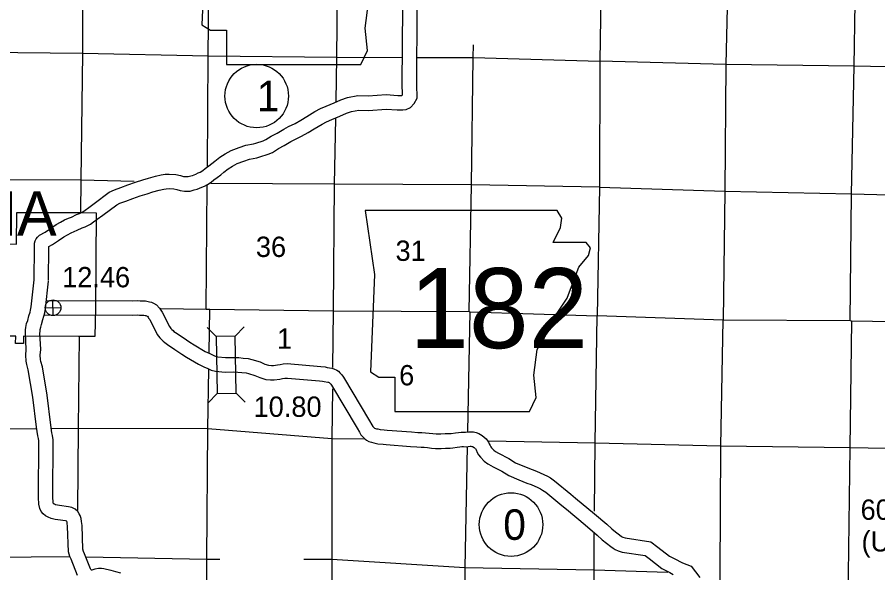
# Model space of a CAD drawing. Extents: x 369523 to 838377, y 495025 to 936819.
# Drawn here: x 502826 to 538589, y 719688 to 742775 of the extents above; entities that cross this region are included whole.
import ezdxf

# ---------------------------------------------------------------- set-up
doc = ezdxf.new("R2010")
doc.units = 0
for name, color, linetype in [('22', 7, 'Continuous'), ('DSN_BRDG_Annotation', 7, 'Continuous'), ('DSN_DRFT_Common-Annotations', 7, 'Continuous'), ('DSN_DRFT_Common-Line', 7, 'Continuous'), ('DSN_DRFT_Junk-No-Plot', 7, 'Continuous'), ('Level 1', 7, 'Continuous'), ('Level 15', 7, 'Continuous'), ('Level 2', 7, 'Continuous'), ('Level 21', 7, 'Continuous'), ('Level 22', 7, 'Continuous')]:
    doc.layers.add(name, color=color, linetype=linetype)

msp = doc.modelspace()

# ---------------------------------------------------------------- linework, layer by layer
at = {"layer": '22'}
for points in [[(510274, 749165), (510674, 746501), (510496, 742460), (510852, 742237), (511518, 742237), (511518, 740816), (517113, 740816), (517380, 741394), (517291, 742326), (517424, 743392), (517913, 744236), (518223, 744858), (518668, 745524), (518934, 746234), (519156, 746812), (519556, 747300), (519645, 747611), (519467, 747833), (518090, 747833), (518401, 748455), (518446, 748854), (518261, 749161)], [(517281, 734741), (517681, 732077), (517504, 728036), (517859, 727814), (518525, 727814), (518525, 726392), (524121, 726392), (524387, 726970), (524298, 727902), (524431, 728968), (524920, 729812), (525231, 730434), (525675, 731100), (525941, 731810), (526163, 732388), (526563, 732876), (526652, 733187), (526474, 733409), (525098, 733409), (525408, 734031), (525453, 734431), (525269, 734737)]]:
    msp.add_lwpolyline(points, close=True, dxfattribs=at)
at = {"layer": 'DSN_DRFT_Common-Annotations'}
for p, q in [((504322, 730377), (504307, 731028)), ((503989, 730695), (504640, 730710))]:
    msp.add_line(p, q, dxfattribs=at)
msp.add_circle((504315, 730703), 326, dxfattribs=at)
at = {"layer": 'DSN_DRFT_Common-Line'}
for centre in [(512780, 739499), (523347, 721691)]:
    msp.add_circle(centre, 1320, dxfattribs=at)
at = {"layer": 'Level 1'}
for points in [[(503524, 731839), (503546, 733218), (503546, 733319), (503549, 733383), (503570, 733478), (503611, 733560), (503663, 733635), (503749, 733713), (503982, 733846), (504209, 733992), (504444, 734159), (504631, 734261), (504797, 734349), (504964, 734425), (505083, 734470), (505290, 734573), (505420, 734618), (505552, 734684), (505644, 734753), (505804, 734864), (506030, 735032), (506648, 735499), (506868, 735604), (507137, 735697), (507421, 735805), (507742, 735923), (508045, 736014), (508285, 736090), (508577, 736172), (508809, 736226), (508968, 736246), (509147, 736256), (509414, 736237), (509615, 736201), (509731, 736161), (509821, 736149), (509929, 736150), (510041, 736179), (510112, 736196), (510250, 736257), (510351, 736302), (510431, 736341), (510534, 736408), (510635, 736492), (510785, 736597), (510909, 736689), (511034, 736796), (511246, 736960), (511470, 737101), (511715, 737239), (512047, 737363), (512333, 737453), (512647, 737520), (512747, 737547), (513051, 737642), (513157, 737687), (513385, 737830), (513623, 737963), (513901, 738129), (514094, 738230), (514371, 738361), (514615, 738499), (514861, 738645), (515201, 738858), (515428, 738975), (515664, 739076), (515997, 739212), (516274, 739337), (516557, 739444), (516982, 739515), (517414, 739503), (518153, 739562), (518644, 739523), (518723, 739524), (518807, 739527), (518822, 739529), (518835, 739545), (518844, 739560), (518830, 739991), (518853, 743187)], [(504124, 731829), (504146, 733214), (504146, 733249), (504294, 733333), (504545, 733494), (504763, 733649), (504915, 733733), (505063, 733811), (505195, 733871), (505323, 733920), (505522, 734019), (505651, 734063), (505869, 734171), (505996, 734267), (506154, 734377), (506390, 734552), (506962, 734983), (507097, 735048), (507342, 735133), (507631, 735243), (507932, 735353), (508222, 735440), (508457, 735515), (508727, 735591), (508914, 735635), (509022, 735648), (509142, 735655), (509338, 735641), (509464, 735618), (509592, 735574), (509785, 735548), (510009, 735552), (510184, 735596), (510304, 735625), (510493, 735709), (510603, 735757), (510729, 735819), (510890, 735925), (510999, 736014), (511136, 736111), (511283, 736220), (511412, 736330), (511590, 736468), (511776, 736585), (511969, 736693), (512242, 736796), (512486, 736872), (512787, 736936), (512914, 736971), (513259, 737078), (513436, 737154), (513690, 737314), (513922, 737443), (514193, 737604), (514362, 737693), (514647, 737828), (514916, 737980), (515173, 738133), (515498, 738336), (515684, 738432), (515895, 738522), (516235, 738661), (516504, 738782), (516714, 738862), (517023, 738914), (517429, 738902), (518154, 738960), (518621, 738923), (518737, 738924), (518857, 738929), (518993, 738946), (519172, 739020), (519327, 739194), (519449, 739412), (519430, 739998), (519453, 743157)], [(503400, 730738), (503526, 731867)], [(503997, 730671), (504122, 731801)], [(504041, 731004), (507603, 730994), (507824, 731003), (507932, 730994), (508069, 730994), (508162, 730983), (508266, 730968), (508327, 730953), (508402, 730930), (508494, 730892), (508612, 730821), (508746, 730681), (508796, 730595), (508851, 730513), (509153, 729921), (509215, 729842), (509258, 729796), (509302, 729757), (509340, 729719), (509411, 729672), (509722, 729465), (509994, 729273), (510179, 729157), (510641, 728884), (510829, 728798), (510996, 728723), (511090, 728680), (511165, 728660), (511486, 728629), (511823, 728635), (512037, 728630), (512217, 728610), (512428, 728589), (512583, 728556), (512919, 728450), (513122, 728360), (513265, 728315), (513394, 728307), (513471, 728303), (513639, 728329), (513760, 728350), (513882, 728365), (514049, 728382), (515442, 728261), (515630, 728244), (515708, 728221), (515899, 728198), (515949, 728175), (515988, 728162), (516112, 728103), (516177, 728061), (516231, 727999), (516311, 727917), (516382, 727823), (517469, 726001), (517559, 725839), (517607, 725766), (517638, 725740), (517678, 725701), (517680, 725699), (517716, 725687), (517762, 725675), (517810, 725669), (517908, 725646), (518081, 725630), (518203, 725620), (519211, 725540), (519476, 725520), (519645, 725512), (519792, 725501), (519942, 725486), (520103, 725470), (520241, 725457), (520429, 725459), (520608, 725471), (520775, 725470), (520855, 725482), (521036, 725506), (521160, 725520), (521272, 725532), (521381, 725532), (521459, 725530), (521599, 725546), (521701, 725552), (521794, 725541), (521906, 725513), (522011, 725470), (522145, 725389), (522236, 725324), (522321, 725251), (522409, 725120), (522441, 725044), (522476, 724972), (522505, 724924), (522536, 724881), (522633, 724781), (522709, 724724), (522834, 724653)], [(505333, 719570), (505062, 720258), (505018, 720370), (504954, 720557), (504920, 721611), (504908, 721744), (504899, 721798), (504892, 721821), (504885, 721832), (504830, 721847), (504515, 721895), (504410, 721904), (504236, 721943), (504107, 721997), (503999, 722060), (503908, 722133), (503826, 722236), (503767, 722359), (503726, 722536), (503706, 722817), (503723, 725173), (503709, 725270), (503681, 725379), (503625, 725746), (503471, 726981), (503286, 728118), (503224, 728347), (503204, 728485), (503186, 728728), (503200, 728964), (503165, 729655), (503177, 729782), (503189, 729879), (503219, 730047), (503262, 730174), (503313, 730372), (503360, 730525), (503384, 730608), (503401, 730743)], [(507126, 719667), (506925, 719729), (506729, 719777), (506537, 719825), (506424, 719848), (506324, 719864), (506208, 719860), (506056, 719837), (505921, 719797), (505911, 719803), (505885, 719825), (505868, 719850), (505621, 720477), (505581, 720578), (505550, 720667), (505519, 721648), (505503, 721819), (505484, 721938), (505444, 722063), (505404, 722134), (505347, 722238), (505230, 722339), (505099, 722397), (504951, 722435), (504587, 722491), (504500, 722499), (504419, 722517), (504376, 722535), (504340, 722556), (504337, 722558), (504322, 722625), (504306, 722837), (504323, 725215), (504298, 725387), (504270, 725498), (504219, 725829), (504065, 727066), (503873, 728245), (503812, 728469), (503800, 728550), (503787, 728732), (503801, 728961), (503766, 729640), (503774, 729717), (503783, 729792), (503801, 729896), (503837, 730001), (503891, 730208), (503936, 730356), (503973, 730489), (503996, 730666)], [(503960, 730404), (507613, 730394), (507811, 730402), (507907, 730394), (508034, 730394), (508085, 730388), (508149, 730379), (508168, 730374), (508200, 730364), (508224, 730355), (508234, 730349), (508264, 730317), (508289, 730275), (508333, 730208), (508645, 729597), (508759, 729452), (508840, 729365), (508891, 729320), (508957, 729254), (509078, 729173), (509382, 728970), (509661, 728773), (509867, 728644), (510363, 728351), (510582, 728251), (510747, 728177), (510888, 728112), (511061, 728067), (511463, 728029), (511821, 728035), (511998, 728031), (512154, 728014), (512335, 727995), (512431, 727975), (512706, 727888), (512911, 727797), (513155, 727721), (513358, 727708), (513501, 727700), (513736, 727737), (513847, 727756), (513949, 727769), (514053, 727780), (515389, 727664), (515516, 727652), (515586, 727631), (515738, 727613), (515762, 727605), (515790, 727592), (515854, 727526), (515883, 727487), (516949, 725701), (517046, 725526), (517112, 725427), (517157, 725359), (517234, 725296), (517274, 725255), (517338, 725203), (517435, 725148), (517543, 725112), (517649, 725084), (517705, 725077), (517810, 725052), (518029, 725032), (518155, 725022), (519165, 724942), (519439, 724921), (519609, 724913), (519741, 724903), (519883, 724889), (520046, 724873), (520216, 724857), (520451, 724859), (520628, 724871), (520816, 724870), (520936, 724887), (521111, 724910), (521226, 724924), (521303, 724932), (521374, 724932), (521487, 724929), (521651, 724948), (521681, 724950), (521684, 724950), (521720, 724941), (521742, 724932), (521815, 724888), (521864, 724853), (521867, 724850), (521879, 724832), (521895, 724796), (521947, 724687), (522002, 724595), (522075, 724494), (522237, 724329), (522380, 724221), (522539, 724131)], [(522823, 724659), (523263, 724434), (523533, 724264), (523911, 724105), (524221, 723975), (524400, 723910), (524709, 723777), (524867, 723700), (524984, 723629), (525154, 723514), (525837, 722952), (526033, 722787), (526815, 722139), (527334, 721703), (527533, 721513), (527685, 721391), (527857, 721262), (527943, 721197), (527970, 721177), (528000, 721165), (528095, 721137), (529155, 720979), (529454, 720757), (529939, 720376), (530239, 720223), (530361, 720153), (530471, 720105), (530838, 719959)], [(522550, 724125), (522965, 723913), (523254, 723730), (523679, 723551), (524003, 723416), (524179, 723352), (524458, 723232), (524579, 723172), (524661, 723123), (524795, 723033), (525453, 722491), (525648, 722327), (526431, 721679), (526933, 721256), (527138, 721061), (527317, 720918), (527496, 720783), (527586, 720715), (527675, 720650), (527800, 720598), (527965, 720550), (528918, 720408), (529090, 720280), (529615, 719868), (529954, 719695), (530092, 719616)], [(530838, 719959), (531195, 719487)]]:
    msp.add_lwpolyline(points, dxfattribs=at)
at = {"layer": 'Level 15'}
for points in [[(516372, 765687), (516335, 762468), (516207, 757164), (516199, 757052), (516208, 751811), (516205, 751676), (516140, 746479), (516146, 746405), (516096, 741115), (516062, 739278)], [(516049, 738567), (516000, 735835), (515954, 730573)], [(508791, 730668), (510682, 730640), (510828, 730637), (515954, 730573), (521602, 730543), (521635, 730537), (526933, 730368)], [(515954, 730573), (515933, 728217)], [(548770, 729900), (548054, 729902), (542754, 730064), (537499, 730147), (537440, 730152), (532170, 730190), (526933, 730368)], [(515924, 727332), (515906, 725270), (515895, 720257), (515881, 714974), (515886, 714633), (515884, 714242)]]:
    msp.add_lwpolyline(points, dxfattribs=at)
at = {"layer": 'Level 2'}
for points in [[(506107, 734646), (506079, 730678), (506048, 729503), (505378, 729501), (503090, 729514), (503085, 729214), (502759, 729216), (502763, 729516), (501441, 729524), (501461, 730723)], [(501461, 730723), (501482, 733354), (502801, 733347), (502811, 734666), (505449, 734657), (506107, 734646)]]:
    msp.add_lwpolyline(points, dxfattribs=at)
at = {"layer": 'Level 21'}
for p, q in [((511097, 729511), (510718, 729879)), ((511889, 729524), (512257, 729903)), ((511135, 727136), (510767, 726757)), ((511927, 727148), (512306, 726781))]:
    msp.add_line(p, q, dxfattribs=at)
msp.add_lwpolyline([(511927, 727148), (511889, 729524), (511097, 729511), (511135, 727136)], close=True, dxfattribs=at)
at = {"layer": 'Level 22'}
for points in [[(510730, 736570), (510763, 741170), (510824, 746460), (510858, 751754), (510883, 757013), (511009, 762376)], [(505616, 757248), (505614, 757065), (505561, 751849), (505545, 746534), (505534, 741280), (505468, 736004), (505454, 734664)], [(527137, 748123), (527121, 746307), (527033, 740945), (527022, 735715), (526933, 730368)], [(532412, 747635), (532399, 746154), (532276, 740810), (532229, 735545), (532170, 730190)], [(537440, 730152), (537497, 735430), (537605, 740739), (537695, 746016), (537695, 747719)], [(521602, 730543), (521705, 735815), (521778, 741099), (521784, 741623)], [(489743, 741352), (495042, 741299), (500149, 741337), (505534, 741280), (510763, 741170), (516096, 741115)], [(516096, 741115), (518812, 741107)], [(519460, 741105), (521778, 741099), (527033, 740945)], [(542381, 740646), (537605, 740739), (532276, 740810), (527033, 740945)], [(507686, 735948), (505468, 736004), (500169, 736012), (494942, 736041), (489640, 736053)], [(510682, 730640), (510724, 735797)], [(516000, 735835), (510871, 735871)], [(527022, 735715), (521705, 735815), (516000, 735835)], [(527022, 735715), (532229, 735545), (537497, 735430), (542772, 735302), (547164, 735247)], [(510800, 728830), (510828, 730637)], [(521635, 730537), (521534, 725555)], [(526816, 722246), (526839, 725095), (526933, 730368)], [(532036, 718612), (532041, 719638), (532073, 724959), (532170, 730190)], [(537499, 730147), (537424, 724900), (537363, 719631), (537276, 716227)], [(505402, 729527), (505360, 725697), (505325, 722294)], [(510696, 718059), (510713, 720257), (510750, 725681), (510789, 728156)], [(490998, 725725), (494557, 725702), (500040, 725639), (503625, 725678)], [(504254, 725685), (505360, 725697), (510750, 725681), (515906, 725270), (517217, 725249)], [(521522, 724937), (521426, 719910), (521424, 714557), (521261, 709274), (521263, 703984), (521219, 701338)], [(522409, 725167), (526839, 725095)], [(526839, 725095), (532073, 724959), (537424, 724900), (542715, 724795), (544659, 724771)], [(526715, 714490), (526796, 719810), (526808, 721343)], [(492362, 720300), (494508, 720292), (500148, 720318), (505020, 720359)], [(505681, 720354), (510713, 720257), (511241, 720257)], [(514741, 720257), (515895, 720257), (521426, 719910), (526796, 719810)], [(526796, 719810), (529863, 719709)]]:
    msp.add_lwpolyline(points, dxfattribs=at)

# ---------------------------------------------------------------- texts
at = {"layer": '22'}
msp.add_text('182', height=3326.4, dxfattribs=at).set_placement((519128, 729023))
at = {"layer": 'DSN_BRDG_Annotation'}
msp.add_text('12.46', height=844.8, dxfattribs=at).set_placement((504692, 731551))
at = {"layer": 'DSN_DRFT_Common-Annotations'}
msp.add_text('OKOLONA', height=1848, dxfattribs=at).set_placement((492242, 733698))
at = {"layer": 'DSN_DRFT_Common-Line'}
for s, p in [('1', (512780, 738865)), ('0', (523024, 721057))]:
    msp.add_text(s, height=1267, dxfattribs=at).set_placement(p)
at = {"layer": 'DSN_DRFT_Junk-No-Plot'}
for s, p in [('10.80', (512648, 726168)), ('60.59', (537874, 721891)), ('(U.P.)', (537913, 720573))]:
    msp.add_text(s, height=844.8, dxfattribs=at).set_placement(p)
at = {"layer": 'Level 22'}
for s, height, p in [('36', 844.8, (512745, 732812)), ('31', 844.8, (518548, 732649)), ('1', 845, (513620, 728999)), ('6', 845, (518698, 727477))]:
    msp.add_text(s, height=height, dxfattribs=at).set_placement(p)

doc.saveas('drawing.dxf')
